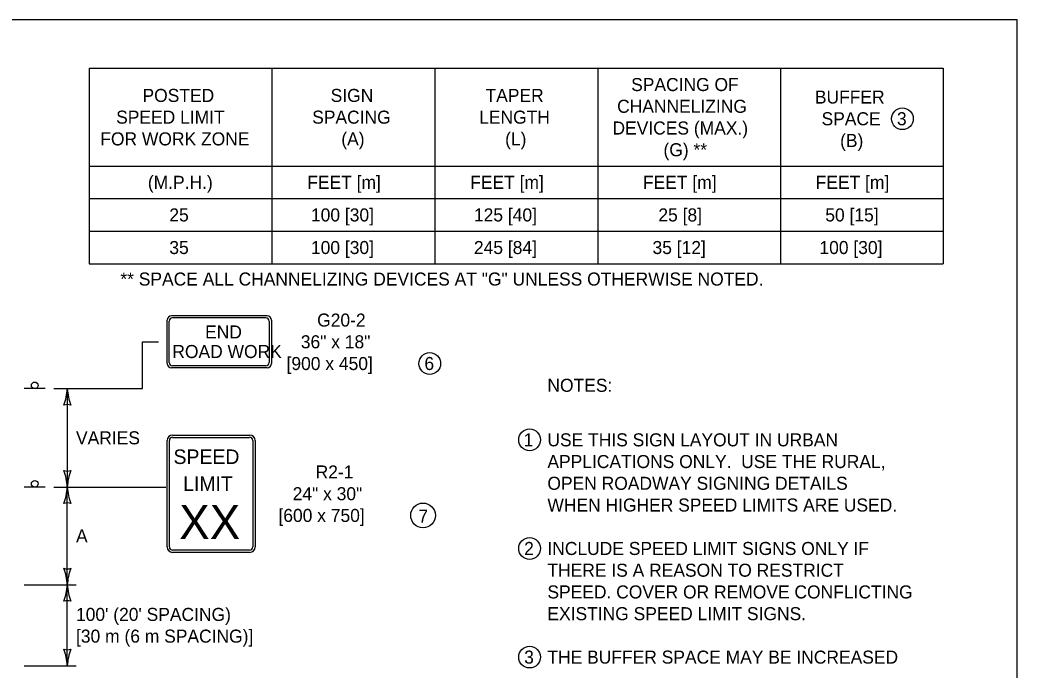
# Model space of a CAD drawing. Extents: x 49991.4 to 50021, y 49987.6 to 50011.4.
# Drawn here: x 50004.026 to 50008.615, y 50008.271 to 50011.263 of the extents above; entities that cross this region are included whole.
import ezdxf

# ---------------------------------------------------------------- set-up
doc = ezdxf.new("R2010")
doc.units = 0
for name, color, linetype in [('Level 1', 7, 'Continuous'), ('Level 2', 7, 'Continuous'), ('Level 3', 7, 'Continuous')]:
    doc.layers.add(name, color=color, linetype=linetype)

msp = doc.modelspace()

# ---------------------------------------------------------------- linework, layer by layer
at = {"layer": 'Level 1'}
for p, q in [((50004.7032, 50009.6815), (50004.7032, 50009.8815)), ((50005.1632, 50009.9015), (50004.7232, 50009.9015)), ((50005.1582, 50009.8915), (50004.7282, 50009.8915)), ((50005.1832, 50009.8815), (50005.1832, 50009.6815)), ((50004.7132, 50009.6865), (50004.7132, 50009.8765)), ((50005.1732, 50009.8765), (50005.1732, 50009.6865)), ((50005.1631, 50009.6614), (50004.7231, 50009.6614)), ((50005.1582, 50009.6715), (50004.7282, 50009.6715)), ((50004.142, 50009.566), (50004.046, 50009.566)), ((50004.7285, 50009.3524), (50005.0829, 50009.3524)), ((50004.7285, 50009.3418), (50005.0829, 50009.3418)), ((50004.9057, 50009.3524), (50004.9057, 50009.3524)), ((50004.7032, 50008.8376), (50004.7032, 50009.3271)), ((50004.7137, 50008.8376), (50004.7137, 50009.3271)), ((50005.0977, 50009.3271), (50005.0977, 50008.8376)), ((50005.1082, 50009.3271), (50005.1082, 50008.8376)), ((50004.142, 50009.1132), (50004.046, 50009.1132)), ((50005.0829, 50008.8229), (50004.7285, 50008.8229)), ((50005.0829, 50008.8123), (50004.7285, 50008.8123))]:
    msp.add_line(p, q, dxfattribs=at)
msp.add_lwpolyline([(50008.6146, 50011.2628), (50000.3356, 50011.2628), (50000.3356, 50000.0624), (50008.6146, 50000.0624)], close=True, dxfattribs=at)
for centre in [(50004.0939, 50009.5811), (50004.0939, 50009.1284)]:
    msp.add_circle(centre, 0.0152, dxfattribs=at)
for centre, radius, start, end in [((50004.7232, 50009.8815), 0.02, 90, 180), ((50004.7282, 50009.8765), 0.015, 90, 180), ((50005.1582, 50009.8765), 0.015, 360, 90), ((50005.1632, 50009.8815), 0.02, 360, 90), ((50004.7231, 50009.6815), 0.02, 180, 270), ((50004.7282, 50009.6865), 0.015, 180, 270), ((50005.1582, 50009.6865), 0.015, 270, 360), ((50005.1631, 50009.6815), 0.02, 270, 360), ((50004.7285, 50009.3271), 0.0253, 90, 180), ((50004.7285, 50009.3271), 0.0148, 90, 180), ((50005.0829, 50009.3271), 0.0253, 0, 90), ((50005.0829, 50009.3271), 0.0148, 0, 90), ((50004.7285, 50008.8376), 0.0253, 180, 270), ((50004.7285, 50008.8376), 0.0148, 180, 270), ((50005.0829, 50008.8376), 0.0148, 270, 360), ((50005.0829, 50008.8376), 0.0253, 270, 360)]:
    msp.add_arc(centre, radius, start, end, dxfattribs=at)
at = {"layer": 'Level 2'}
for p, q in [((50004.3453, 50011.0404), (50008.2753, 50011.0404)), ((50004.3453, 50011.0404), (50004.3453, 50010.1404)), ((50005.1853, 50011.0404), (50005.1853, 50010.1404)), ((50005.9353, 50011.0404), (50005.9353, 50010.1404)), ((50006.6853, 50011.0404), (50006.6853, 50010.1404)), ((50007.5253, 50011.0404), (50007.5253, 50010.1404)), ((50008.2753, 50011.0404), (50008.2753, 50010.1404)), ((50004.3453, 50010.5904), (50008.2753, 50010.5904)), ((50004.3453, 50010.4404), (50008.2753, 50010.4404)), ((50004.3453, 50010.2904), (50008.2753, 50010.2904)), ((50004.3453, 50010.1404), (50008.2753, 50010.1404))]:
    msp.add_line(p, q, dxfattribs=at)
for centre, radius in [((50008.0869, 50010.808), 0.0501), ((50005.9117, 50009.6815), 0.0501), ((50006.3715, 50009.3304), 0.0501), ((50005.8811, 50008.9824), 0.0569), ((50006.3715, 50008.8304), 0.0501), ((50006.3715, 50008.3304), 0.0501)]:
    msp.add_circle(centre, radius, dxfattribs=at)
at = {"layer": 'Level 3'}
for p, q in [((50004.182, 50009.566), (50004.5906, 50009.566)), ((50004.244, 50009.566), (50004.244, 50009.1132)), ((50004.182, 50009.1132), (50004.6308, 50009.1132)), ((50004.244, 50008.6632), (50004.244, 50009.1132)), ((50004.046, 50008.6632), (50004.284, 50008.6632)), ((50004.244, 50008.2906), (50004.244, 50008.6632)), ((50004.046, 50008.2906), (50004.284, 50008.2906))]:
    msp.add_line(p, q, dxfattribs=at)
for points in [[(50004.5906, 50009.566), (50004.5906, 50009.7816), (50004.6632, 50009.7816)], [(50004.6274, 50009.1132), (50004.6971, 50009.1132)]]:
    msp.add_lwpolyline(points, dxfattribs=at)
for centre, radius, start, end in [((50004.0219, 50009.5751), 0.2223, 337.456, 357.6395), ((50004.4767, 50009.5775), 0.233, 182.8273, 202.0772), ((50004.244, 50009.4378), 0.0548, 72.1388, 107.8612), ((50004.244, 50009.2414), 0.0548, 252.1388, 287.8612), ((50004.0113, 50009.1017), 0.233, 2.8273, 22.0772), ((50004.4661, 50009.104), 0.2223, 157.456, 177.6395), ((50004.0219, 50009.1224), 0.2223, 337.456, 357.6395), ((50004.4767, 50009.1247), 0.233, 182.8273, 202.0772), ((50004.244, 50008.985), 0.0548, 72.1388, 107.8612), ((50004.244, 50008.7914), 0.0548, 252.1388, 287.8612), ((50004.0113, 50008.6517), 0.233, 2.8273, 22.0772), ((50004.4661, 50008.654), 0.2223, 157.456, 177.6395), ((50004.0219, 50008.6724), 0.2223, 337.456, 357.6395), ((50004.4767, 50008.6747), 0.233, 182.8273, 202.0772), ((50004.244, 50008.535), 0.0548, 72.1388, 107.8612), ((50004.244, 50008.4188), 0.0548, 252.1388, 287.8612), ((50004.0113, 50008.2791), 0.233, 2.8273, 22.0772), ((50004.4661, 50008.2814), 0.2223, 157.456, 177.6395)]:
    msp.add_arc(centre, radius, start, end, dxfattribs=at)

# ---------------------------------------------------------------- texts
at = {"layer": 'Level 1'}
for s, p in [('END', (50004.878, 50009.7968)), ('ROAD WORK', (50004.7273, 50009.7068))]:
    msp.add_text(s, height=0.06, rotation=360, dxfattribs=at).set_placement(p)
for s, height, p in [('SPEED', 0.06695, (50004.7326, 50009.2191)), ('LIMIT', 0.06695, (50004.7769, 50009.0954)), ('XX', 0.15772, (50004.7586, 50008.8734))]:
    msp.add_text(s, height=height, dxfattribs=at).set_placement(p)
at = {"layer": 'Level 2'}
for s, p in [('SPACING OF', (50006.8388, 50010.9354)), ('POSTED', (50004.59, 50010.8854)), ('SIGN', (50005.4559, 50010.8854)), ('TAPER', (50006.1686, 50010.8854)), ('BUFFER', (50007.6842, 50010.878)), ('CHANNELIZING', (50006.7741, 50010.8354)), ('SPEED LIMIT', (50004.4687, 50010.7854)), ('SPACING', (50005.3709, 50010.7854)), ('LENGTH', (50006.1394, 50010.7854)), ('DEVICES (MAX.)', (50006.7527, 50010.7354)), ('SPACE', (50007.715, 50010.778)), ('3', (50008.0619, 50010.7781)), ('FOR WORK ZONE', (50004.3957, 50010.6854)), ('(A)', (50005.5049, 50010.6854)), ('(L)', (50006.2587, 50010.6854)), ('(B)', (50007.8002, 50010.678)), ('(G) **', (50006.9874, 50010.6354)), ('(M.P.H.)', (50004.6146, 50010.4854)), ('FEET [m]', (50005.348, 50010.4854)), ('FEET [m]', (50006.098, 50010.4854)), ('FEET [m]', (50006.893, 50010.4854)), ('FEET [m]', (50007.688, 50010.4854)), ('25', (50004.7135, 50010.3354)), ('100 [30]', (50005.3652, 50010.3354)), ('125 [40]', (50006.1152, 50010.3354)), ('25 [8]', (50006.964, 50010.3354)), ('50 [15]', (50007.7321, 50010.3354)), ('35', (50004.7135, 50010.1854)), ('100 [30]', (50005.3652, 50010.1854)), ('245 [84]', (50006.1152, 50010.1854)), ('35 [12]', (50006.9371, 50010.1854)), ('100 [30]', (50007.7052, 50010.1854)), ('** SPACE ALL CHANNELIZING DEVICES AT "G" UNLESS OTHERWISE NOTED.', (50004.4881, 50010.0404)), ('G20-2', (50005.3937, 50009.8515)), ('36" x 18"', (50005.3185, 50009.7515)), ('[900 x 450]', (50005.2529, 50009.6515)), ('6', (50005.8874, 50009.6516)), ('NOTES:', (50006.4533, 50009.5513)), ('1', (50006.3438, 50009.3003)), ('USE THIS SIGN LAYOUT IN URBAN', (50006.4533, 50009.3003)), ('APPLICATIONS ONLY.  USE THE RURAL,', (50006.4533, 50009.2003)), ('R2-1', (50005.3867, 50009.1524)), ('OPEN ROADWAY SIGNING DETAILS ', (50006.4533, 50009.1003)), ('24" x 30"', (50005.2811, 50009.0524)), ('WHEN HIGHER SPEED LIMITS ARE USED.', (50006.4533, 50009.0003)), ('[600 x 750]', (50005.2156, 50008.9524)), ('7', (50005.8594, 50008.9487)), ('A', (50004.284, 50008.8582)), ('2', (50006.3464, 50008.8004)), ('INCLUDE SPEED LIMIT SIGNS ONLY IF ', (50006.4533, 50008.8003)), ('THERE IS A REASON TO RESTRICT', (50006.4533, 50008.7003)), ('SPEED. COVER OR REMOVE CONFLICTING', (50006.4533, 50008.6003)), ("100' (20' SPACING)", (50004.284, 50008.4969)), ('EXISTING SPEED LIMIT SIGNS.', (50006.4533, 50008.5003)), ('[30 m (6 m SPACING)]', (50004.284, 50008.3969)), ('3', (50006.3464, 50008.3004)), ('THE BUFFER SPACE MAY BE INCREASED ', (50006.4533, 50008.3003))]:
    msp.add_text(s, height=0.06, dxfattribs=at).set_placement(p)
msp.add_text('VARIES', height=0.06, rotation=360, dxfattribs=at).set_placement((50004.284, 50009.3096))

doc.saveas('drawing.dxf')
